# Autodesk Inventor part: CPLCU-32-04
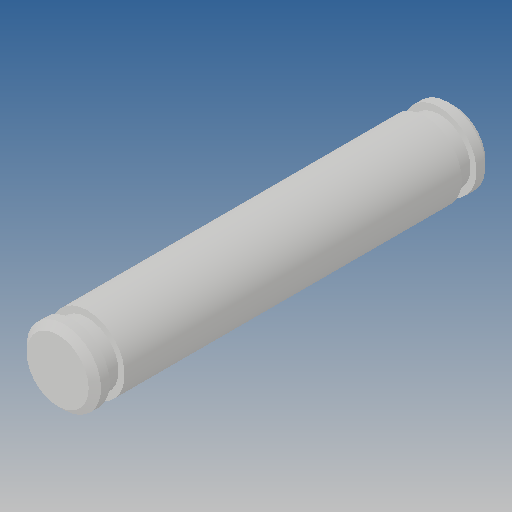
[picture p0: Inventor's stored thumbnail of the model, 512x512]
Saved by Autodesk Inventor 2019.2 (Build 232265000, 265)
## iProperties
Created: 2010-03
Part Number: CPLCU-32-04
Material: Ogólny
Document SubType Name: Modeling
Designer: CADENGINEERING4
Density: 1 g/cm^3
Appearance: Domyślna
Author: CADENGINEERING4
Revision Number: 3LAST_VERSION
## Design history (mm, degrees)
feature "Baza1"
node "Bryła1"
